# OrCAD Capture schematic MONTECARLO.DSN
size A
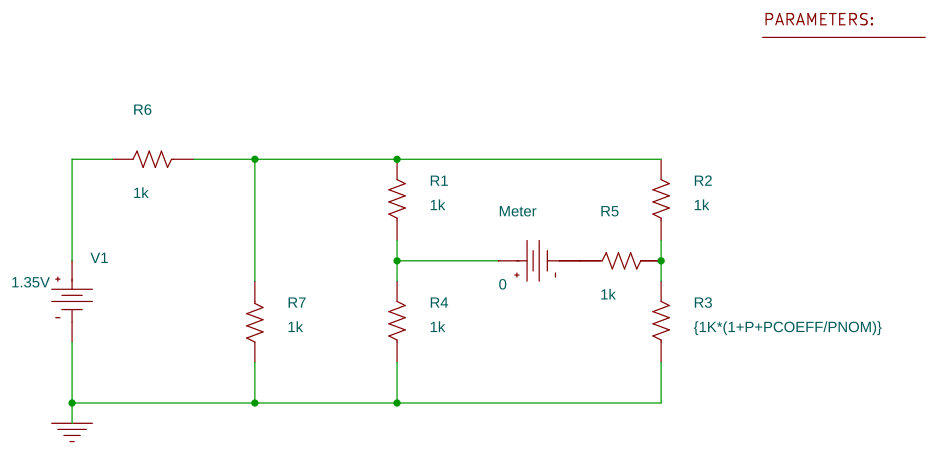
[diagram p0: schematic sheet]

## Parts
1  PARAM
Meter  VDC
R1  1k
R2  1k
R3  {1K*(1+P+PCOEFF/PNOM)}
R4  1k
R5  1k  [RC05]
R6  1k  [RC05]
R7  1k  [RC05]
V1  VDC

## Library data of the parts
1 = PARAM: P: 0; PCOEFF: -0.06; PNOM: 1.0
Meter = VDC: DC: 0
R1-R4 = Rbreak
R5-R7 = R
V1 = VDC: DC: 1.35V

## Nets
0: R3.1 R4.1 R7.2 V1.1(-)
N00282: Meter.1(-) R5.1
N00284: R6.2 V1.0(+)
N00291: R1.0(2) R2.0(2) R6.1 R7.1
N00336: Meter.0(+) R1.1 R4.0(2)
N00350: R2.1 R3.0(2) R5.2
